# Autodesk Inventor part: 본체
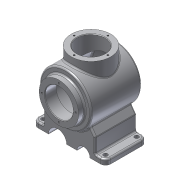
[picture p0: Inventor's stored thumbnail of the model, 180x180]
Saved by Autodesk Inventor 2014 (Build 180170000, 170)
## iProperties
Created: 2018-08
Part Number: 본체
Material: 알루미늄 6061
Document SubType Name: Modeling
Designer: 601-24
Density: 2.71 g/cm^3
Appearance: 알루미늄 - 평지
Mass: 1886.42 g
Surface Area: 1085.74 cm^2
Volume: 696.096 cm^3
Author: 601-24
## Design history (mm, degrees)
sketch "스케치1"
  geometry: L1 (-54, 50)-(42.671, 50); L2 (54, 50)-(54, 0); L3 (54, 0)-(-54, 0); L4 (-54, 0)-(-54, 50); L5 (-54, -50)-(42.671, -50); L6 (54, -50)-(54, 0); L7 (-54, 0)-(-54, -50); L8 (42.671, 50)-(54, 50); L9 (42.671, -50)-(54, -50); A1 r 116 centre (-62, 0) between (42.671, -50) and (42.671, 50); 2 further points
  constraints: 18 end point, 3 parallel, 3 point on circle, 2 horizontal, 2 perpendicular, 2 symmetric about line, 1 centre point, 1 coincident, 1 midpoint, 1 tangent
  dimensions: "d0" = 100 diameter of L1 L3; "d1" = 108 distance of L1.start L2.start; "d2" = 232 diameter of A1
revolve "회전1" sketch "스케치1" stored, may be unused: angle "d3" = 90 deg
sketch "스케치14"
  geometry: L1 (-54, 50)-(54, 50); L2 (54, 50)-(54, 0); L3 (54, 0)-(-54, 0); L4 (-54, 0)-(-54, 50); L5 (-54, 50)-(42.671, 50) reference; 2 further points
  constraints: 8 end point, 2 parallel, 1 coincident, 1 collinear, 1 horizontal, 1 midpoint, 1 perpendicular
  dimensions: "d85" = 108 distance of L1.start L1.end
revolve "회전7" sketch "스케치14" stored, may be unused: angle "d86" = 90 deg
sketch "스케치5"
  geometry: L1 (-42, 64.768)-(-4, 64.768); L2 (-4, 64.768)-(-4, -0.232); L3 (-4, -0.232)-(-42, -0.232); L4 (-42, -0.232)-(-42, 64.768); L5 (-54, -50)-(-54, 50) reference
  constraints: 8 end point, 2 parallel, 1 horizontal, 1 perpendicular
  dimensions: "d57" = 50 distance between parallel lines of L2 L5; "d58" = 65 distance of L3.end L1.start; "d59" = 76 diameter of L4 L2
revolve "회전5" sketch "스케치5" stored, may be unused: angle "d27" = 90 deg
sketch "스케치3"
  geometry: L1 (-54, -50)-(-54, 50) reference; L2 (-66, 38)-(-54, 38); L3 (-54, 38)-(-54, 0); L4 (-54, 0)-(-66, 0); L5 (-66, 0)-(-66, 38); 1 further point
  constraints: 8 end point, 2 parallel, 1 horizontal, 1 midpoint, 1 perpendicular
  dimensions: "d10" = 76 diameter of L2 L4; "d11" = 12 distance of L2.start L2.end
revolve "회전3" sketch "스케치3" stored, may be unused: angle "d12" = 90 deg
sketch "스케치2"
  geometry: L1 (-54, 50)-(42.671, 50) reference; L2 (-54, -50)-(-54, 50) reference; L3 (-54, -50)-(42.671, -50) reference; L4 (36.163, 40)-(-44, 40); L5 (-44, 40)-(-44, 0); L6 (-54, 0)-(44, 0); L7 (-54, -38)-(-54, 38) reference; L8 (-66, -38)-(-66, 38) reference; L9 (-66, 27)-(-44, 27); L10 (-44, 27)-(-44, 0); L11 (-44, 0)-(-66, 0); L12 (-66, 0)-(-66, 27); A1 r 116 centre (-62, 0) between (42.671, -50) and (42.671, 50) reference; A2 r 106 centre (-62, 0) between (44, 0) and (36.163, 40); 2 further points
  constraints: 14 end point, 3 point on line, 2 parallel, 2 point on circle, 1 centre point, 1 collinear, 1 horizontal, 1 midpoint, 1 perpendicular
  dimensions: "d4" = 10 distance between parallel lines of L1 L4; "d6" = 10 radial gap between concentric circles of A1 A2; "d13" = 22 distance of L9.start L9.end; "d14" = 54 diameter of L9 L11; "d70" = 80 diameter of L4 L6 (derived)
revolve "회전4" sketch "스케치2" stored, may be unused: angle "d15" = 90 deg
sketch "스케치6"
  geometry: L1 (-42, 64.768)-(34, 64.768) reference; L2 (-31, 64.768)-(-4, 64.768); L3 (-4, 64.768)-(-4, 0); L4 (-4, 0)-(-31, 0); L5 (-31, 0)-(-31, 64.768); L6 (-54, -50)-(-54, 50) reference; 1 further point
  constraints: 8 end point, 2 parallel, 1 horizontal, 1 perpendicular, 1 point on line
  dimensions: "d60" = 50 distance between parallel lines of L3 L6; "d61" = 54 diameter of L5 L3
revolve "회전6" sketch "스케치6" stored, may be unused: angle "d29" = 90 deg
sketch "스케치4"
  geometry: C1 r 38 at (0, 0) reference; A1 r 32.5 centre (0, 0) between (0, 32.5) and (-32.5, 0); 2 further points
  constraints: 4 point on circle, 1 centre point, 1 coincident
  dimensions: "d16" = 65 diameter of A1
hole "구멍1" sketch "스케치4" at (0, 32.5), (-32.5, 0), (32.5, 0), (0, -32.5) diameter "d17" = 3.242; stored, may be unused: countersink angle "d21" = 90 deg, drill point angle "d23" = 118 deg; dims "d18" = 8, "d19" = 4, "d20" = 2, "d22" = 10
node "작업 평면1"
sketch "스케치9"
  geometry: L1 (70, -72)-(70, -82.232); L2 (-70, -82.232)-(-70, -72.232); L3 (0, 0)-(0, -82); L4 (-50, -72.232)-(-50, -43.437); L5 (50, -72)-(50, -43.437); L6 (-50, -43.437)-(-40.304, -29.59); L7 (40.304, -29.59)-(50, -43.437); L8 (-70, -72.232)-(-50, -72.232); L9 (50, -72)-(70, -72); L10 (70, -82.232)-(39.998, -82.232); L11 (15, -82)-(-5, -82); L12 (-39.998, -82.232)-(-70, -82.232); L13 (-38, 64.768)-(38, 64.768) reference; A1 r 50 centre (0, 0) between (-40.304, -29.59) and (40.304, -29.59) reference; A2 r 12.5 centre (27.5, -82) between (39.998, -82.232) and (15, -82); A3 r 17.5 centre (-22.5, -82) between (-5, -82) and (-39.998, -82.232)
  constraints: 24 end point, 10 parallel, 6 point on circle, 2 centre point, 2 horizontal, 2 perpendicular, 1 point on line
  dimensions: "d39" = 10 distance of L2.start L2.end; "d40" = 82 distance of L3.end L3.start; "d41" = 20 distance between parallel lines of L2 L4; "d42" = 20 distance between parallel lines of L1 L5; "d43" = 140 distance of L1.end L2.start; "d46" = 35 deg angle of L1 L7; "d47" = 35 deg angle of L6 L2; "d48" = 25 diameter of A2; "d49" = 35 diameter of A3; "d50" = 27.5 distance from line of L3 A2.centre; "d51" = 22.5 distance from line of A3.centre L3; "d91" = 147 distance between parallel lines of L13 L12
extrude "돌출1" join sketch "스케치9" distance "d52" = 80; taper "d53" = 0 deg
sketch "스케치11"
  geometry: C1 r 38 at (0, 0); A1 r 32.5 centre (0, 0) between (0, 32.5) and (-32.5, 0); 2 further points
  constraints: 4 point on circle, 2 centre point, 1 coincident
  dimensions: "d63" = 65 diameter of A1
hole "구멍3" sketch "스케치11" at (0, 32.5), (-32.5, 0), (32.5, 0), (0, -32.5) diameter "d69" = 3.242; stored, may be unused: drill point angle "d64" = 118 deg, countersink angle "d65" = 90 deg; dims "d62" = 8, "d66" = 2, "d67" = 4, "d68" = 10
fillet "모깎기1" dims "d71" = 10
sketch "스케치12"
  geometry: A1 r 10 centre (10, 70) between (20, 70) and (10, 80) reference; A2 r 10 centre (10, 10) between (10, 0) and (20, 10) reference; A3 r 10 centre (-110, 70) between (-110, 80) and (-120, 70) reference; A4 r 10 centre (-110, 10) between (-120, 10) and (-110, 0) reference; 5 further points
  constraints: 4 coincident
hole "구멍4" sketch "스케치12" at (10, 70), (10, 10), (-110, 70), (-110, 10) diameter "d72" = 8; stored, may be unused: countersink angle "d76" = 90 deg, drill point angle "d78" = 118 deg; dims "d73" = 8, "d74" = 4, "d75" = 2, "d77" = 10
fillet "모깎기2" dims "d79" = 3
fillet "모깎기3" dims "d80" = 3
chamfer "모따기1" distance "d81" = 1; stored, may be unused: second distance "d82" = 2, angle "d83" = 45 deg
node "작업 평면2"
sketch "스케치15"
  geometry: L1 (54, -50)-(54, 50) reference; L2 (-51, 50)-(54, 50) reference; L3 (-51, -50)-(54, -50) reference; L4 (-177.739, 0)-(54, 0); A1 r 116 centre (-62, 0) between (42.671, -50) and (42.671, 50); 1 further point
  constraints: 3 point on circle, 3 point on line, 2 end point, 1 centre point, 1 midpoint, 1 parallel
  dimensions: "d88" = 232 diameter of A1
revolve "회전8" sketch "스케치15" stored, may be unused: angle "d89" = 90 deg
fillet "모깎기4" dims "d90" = 3
node "솔리드1"
node "투영된 루프1"
other parameters: "d38" = -8
